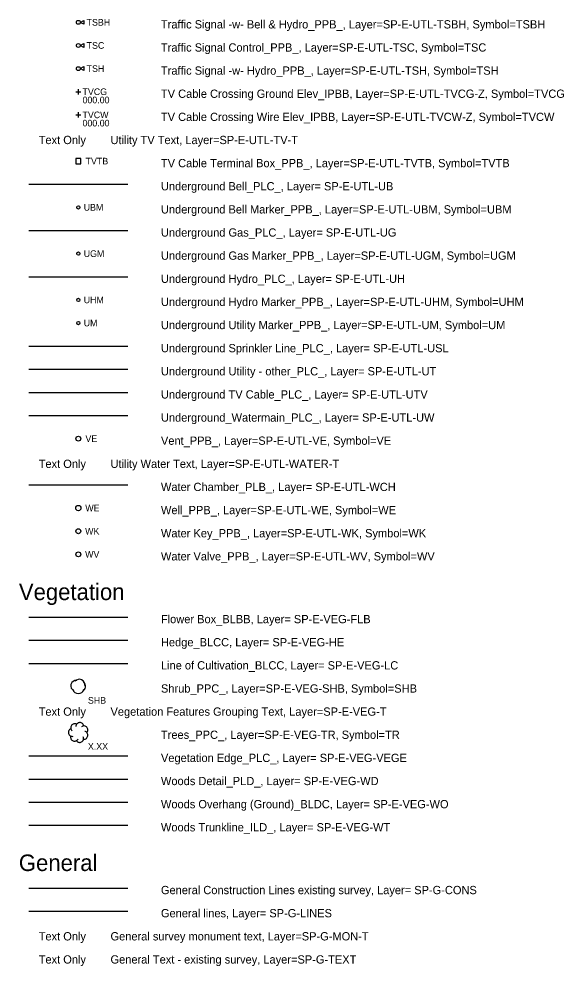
# Model space of a CAD drawing. Extents: x 500528 to 502626, y 4210261 to 4212624.
# Drawn here: x 501383.6 to 501548.5, y 4210563 to 4210849.6 of the extents above; entities that cross this region are included whole.
import ezdxf

# ---------------------------------------------------------------- set-up
doc = ezdxf.new("R2010")
doc.units = 0
for name, color, linetype in [('Default', 7, 'Continuous'), ('SP-E-UTL-BELL-T', 7, 'Continuous'), ('SP-E-UTL-COMB-T', 7, 'Continuous'), ('SP-E-UTL-GAS-T', 7, 'Continuous'), ('SP-E-UTL-HYDRO-T', 7, 'Continuous'), ('SP-E-UTL-T', 7, 'Continuous'), ('SP-E-UTL-TRAFFIC-T', 7, 'Continuous'), ('SP-E-UTL-TSBH', 7, 'Continuous'), ('SP-E-UTL-TSC', 7, 'Continuous'), ('SP-E-UTL-TSH', 7, 'Continuous'), ('SP-E-UTL-TV-T', 7, 'Continuous'), ('SP-E-UTL-TVCG-Z', 7, 'Continuous'), ('SP-E-UTL-TVCW-Z', 7, 'Continuous'), ('SP-E-UTL-TVTB', 7, 'Continuous'), ('SP-E-UTL-UB', 7, 'Continuous'), ('SP-E-UTL-UBM', 7, 'Continuous'), ('SP-E-UTL-UG', 7, 'Continuous'), ('SP-E-UTL-UGM', 7, 'Continuous'), ('SP-E-UTL-UH', 7, 'Continuous'), ('SP-E-UTL-UHM', 7, 'Continuous'), ('SP-E-UTL-UM', 7, 'Continuous'), ('SP-E-UTL-USL', 7, 'Continuous'), ('SP-E-UTL-UT', 7, 'Continuous'), ('SP-E-UTL-UTV', 7, 'Continuous'), ('SP-E-UTL-UW', 7, 'Continuous'), ('SP-E-UTL-VE', 7, 'Continuous'), ('SP-E-UTL-WATER-T', 7, 'Continuous'), ('SP-E-UTL-WCH', 7, 'Continuous'), ('SP-E-UTL-WE', 7, 'Continuous'), ('SP-E-UTL-WK', 7, 'Continuous'), ('SP-E-UTL-WV', 7, 'Continuous'), ('SP-E-VEG-FLB', 7, 'Continuous'), ('SP-E-VEG-HE', 7, 'Continuous'), ('SP-E-VEG-LC', 7, 'Continuous'), ('SP-E-VEG-SHB', 7, 'Continuous'), ('SP-E-VEG-T', 7, 'Continuous'), ('SP-E-VEG-TR', 7, 'Continuous'), ('SP-E-VEG-VEGE', 7, 'Continuous'), ('SP-E-VEG-WD', 7, 'Continuous'), ('SP-E-VEG-WO', 7, 'Continuous'), ('SP-E-VEG-WT', 7, 'Continuous'), ('SP-G-CONS', 7, 'Continuous'), ('SP-G-LINES', 7, 'Continuous'), ('SP-G-MON-T', 7, 'Continuous'), ('SP-G-TEXT', 7, 'Continuous')]:
    doc.layers.add(name, color=color, linetype=linetype)

# ---------------------------------------------------------------- blocks, each defined once
blk = doc.blocks.new('TSBH')
at = {"layer": 'SP-E-UTL-TSBH'}
for points in [[(0, 0), (0, 0)], [(0.058, 0), (0.162, 0.06), (0.162, -0.06), (0.058, 0)]]:
    blk.add_lwpolyline(points, dxfattribs=at)
blk.add_circle((0, 0), 0.0585, dxfattribs=at)
at = {"layer": 'SP-E-UTL-COMB-T'}
blk.add_text('TSBH', height=0.2, dxfattribs=at).set_placement((0.251, -0.1))
blk = doc.blocks.new('TSC')
at = {"layer": 'SP-E-UTL-TSC'}
for points in [[(0, 0), (0, 0)], [(0.058, 0), (0.162, 0.06), (0.162, -0.06), (0.058, 0)]]:
    blk.add_lwpolyline(points, dxfattribs=at)
blk.add_circle((0, 0), 0.0585, dxfattribs=at)
at = {"layer": 'SP-E-UTL-TRAFFIC-T'}
blk.add_text('TSC', height=0.2, dxfattribs=at).set_placement((0.251, -0.1))
blk = doc.blocks.new('TSH')
at = {"layer": 'SP-E-UTL-TSH'}
for points in [[(0, 0), (0, 0)], [(0.058, 0), (0.162, 0.06), (0.162, -0.06), (0.058, 0)]]:
    blk.add_lwpolyline(points, dxfattribs=at)
blk.add_circle((0, 0), 0.0585, dxfattribs=at)
at = {"layer": 'SP-E-UTL-COMB-T'}
blk.add_text('TSH', height=0.2, dxfattribs=at).set_placement((0.251, -0.1))
blk = doc.blocks.new('TVCG')
at = {"layer": 'SP-E-UTL-TVCG-Z'}
for points in [[(-0.08, 0), (0.08, 0)], [(0, -0.08), (0, 0.08)]]:
    blk.add_lwpolyline(points, dxfattribs=at)
at = {"layer": 'SP-E-UTL-TV-T'}
for s, p in [('TVCG', (0.126, -0.1)), ('000.00', (0.126, -0.35))]:
    blk.add_text(s, height=0.2, dxfattribs=at).set_placement(p)
blk = doc.blocks.new('TVCW')
at = {"layer": 'SP-E-UTL-TVCW-Z'}
for points in [[(-0.08, 0), (0.08, 0)], [(0, -0.08), (0, 0.08)]]:
    blk.add_lwpolyline(points, dxfattribs=at)
at = {"layer": 'SP-E-UTL-TV-T'}
for s, p in [('TVCW', (0.126, -0.1)), ('000.00', (0.126, -0.35))]:
    blk.add_text(s, height=0.2, dxfattribs=at).set_placement(p)
blk = doc.blocks.new('TVTB')
at = {"layer": 'SP-E-UTL-TVTB'}
blk.add_lwpolyline([(-0.08, 0.08), (-0.08, -0.08), (0.08, -0.08), (0.08, 0.08), (-0.08, 0.08)], dxfattribs=at)
at = {"layer": 'SP-E-UTL-TV-T'}
blk.add_text('TVTB', height=0.2, dxfattribs=at).set_placement((0.22, -0.1))
blk = doc.blocks.new('UBM')
at = {"layer": 'SP-E-UTL-UBM'}
blk.add_lwpolyline([(0, 0), (0, 0)], dxfattribs=at)
blk.add_circle((0, 0), 0.05, dxfattribs=at)
at = {"layer": 'SP-E-UTL-BELL-T'}
blk.add_text('UBM', height=0.2, dxfattribs=at).set_placement((0.162, -0.1))
blk = doc.blocks.new('UGM')
at = {"layer": 'SP-E-UTL-UGM'}
blk.add_lwpolyline([(0, 0), (0, 0)], dxfattribs=at)
blk.add_circle((0, 0), 0.05, dxfattribs=at)
at = {"layer": 'SP-E-UTL-GAS-T'}
blk.add_text('UGM', height=0.2, dxfattribs=at).set_placement((0.162, -0.1))
blk = doc.blocks.new('UHM')
at = {"layer": 'SP-E-UTL-UHM'}
blk.add_lwpolyline([(0, 0), (0, 0)], dxfattribs=at)
blk.add_circle((0, 0), 0.05, dxfattribs=at)
at = {"layer": 'SP-E-UTL-HYDRO-T'}
blk.add_text('UHM', height=0.2, dxfattribs=at).set_placement((0.162, -0.1))
blk = doc.blocks.new('UM')
at = {"layer": 'SP-E-UTL-UM'}
blk.add_lwpolyline([(0, 0), (0, 0)], dxfattribs=at)
blk.add_circle((0, 0), 0.05, dxfattribs=at)
at = {"layer": 'SP-E-UTL-T'}
blk.add_text('UM', height=0.2, dxfattribs=at).set_placement((0.162, -0.1))
blk = doc.blocks.new('VE')
at = {"layer": 'SP-E-UTL-VE'}
blk.add_lwpolyline([(0, 0), (0, 0)], dxfattribs=at)
blk.add_circle((0, 0), 0.075, dxfattribs=at)
at = {"layer": 'SP-E-UTL-T'}
blk.add_text('VE', height=0.2, dxfattribs=at).set_placement((0.215, -0.1))
blk = doc.blocks.new('WE')
at = {"layer": 'SP-E-UTL-WE'}
blk.add_lwpolyline([(0, 0), (0, 0)], dxfattribs=at)
blk.add_circle((0, 0), 0.08, dxfattribs=at)
at = {"layer": 'SP-E-UTL-T'}
blk.add_text('WE', height=0.2, dxfattribs=at).set_placement((0.211, -0.1))
blk = doc.blocks.new('WK')
at = {"layer": 'SP-E-UTL-WK'}
blk.add_lwpolyline([(0, 0), (0, 0)], dxfattribs=at)
blk.add_circle((0, 0), 0.075, dxfattribs=at)
at = {"layer": 'SP-E-UTL-WATER-T'}
blk.add_text('WK', height=0.2, dxfattribs=at).set_placement((0.206, -0.1))
blk = doc.blocks.new('WV')
at = {"layer": 'SP-E-UTL-WV'}
blk.add_lwpolyline([(0, 0), (0, 0)], dxfattribs=at)
blk.add_circle((0, 0), 0.075, dxfattribs=at)
at = {"layer": 'SP-E-UTL-WATER-T'}
blk.add_text('WV', height=0.2, dxfattribs=at).set_placement((0.206, -0.1))
blk = doc.blocks.new('SHB')
at = {"layer": 'SP-E-VEG-SHB'}
for centre, radius, start, end in [((-0.069, 0.02), 0.161, 80.6965, 246.9293), ((0.031, 0.052), 0.166, 353.6146, 139.6631), ((0.045, 0.007), 0.172, 296.4869, 48.0431), ((0, -0.044), 0.172, 193.3596, 346.7738)]:
    blk.add_arc(centre, radius, start, end, dxfattribs=at)
at = {"layer": 'SP-E-VEG-T'}
blk.add_text('SHB', height=0.2, dxfattribs=at).set_placement((0.29, -0.52))
blk = doc.blocks.new('TR')
at = {"layer": 'SP-E-VEG-TR'}
for points in [[(0.165, 0.205), (0.16, 0.227), (0.15, 0.247), (0.138, 0.266), (0.122, 0.281), (0.103, 0.293), (0.082, 0.302), (0.061, 0.307), (0.038, 0.307), (0.016, 0.304), (-0.005, 0.296), (-0.024, 0.285), (-0.041, 0.27), (-0.054, 0.252), (-0.065, 0.233), (-0.071, 0.211), (-0.074, 0.189)], [(-0.226, 0.123), (-0.246, 0.113), (-0.264, 0.099), (-0.279, 0.083), (-0.29, 0.064), (-0.298, 0.043), (-0.302, 0.021), (-0.302, -0.001), (-0.297, -0.023), (-0.289, -0.044), (-0.277, -0.063), (-0.261, -0.079), (-0.243, -0.092), (-0.223, -0.102), (-0.202, -0.107), (-0.179, -0.109), (-0.157, -0.106)], [(-0.05, 0.258), (-0.071, 0.268), (-0.092, 0.273), (-0.115, 0.274), (-0.137, 0.272), (-0.158, 0.265), (-0.177, 0.254), (-0.195, 0.24), (-0.209, 0.223), (-0.22, 0.203), (-0.227, 0.182), (-0.23, 0.16), (-0.229, 0.138), (-0.224, 0.116), (-0.215, 0.096), (-0.202, 0.077), (-0.187, 0.062)], [(0.258, 0.004), (0.272, 0.022), (0.282, 0.041), (0.288, 0.063), (0.29, 0.085), (0.288, 0.107), (0.282, 0.129), (0.272, 0.149), (0.259, 0.166), (0.242, 0.181), (0.223, 0.193), (0.202, 0.201), (0.18, 0.205), (0.158, 0.205), (0.136, 0.201), (0.115, 0.192), (0.096, 0.18)], [(0.158, -0.194), (0.181, -0.194), (0.203, -0.19), (0.223, -0.181), (0.242, -0.169), (0.258, -0.153), (0.271, -0.135), (0.28, -0.115), (0.286, -0.093), (0.287, -0.071), (0.285, -0.049), (0.278, -0.028), (0.267, -0.008), (0.253, 0.009), (0.236, 0.024), (0.217, 0.035), (0.196, 0.042)], [(-0.23, -0.099), (-0.234, -0.121), (-0.235, -0.143), (-0.231, -0.165), (-0.224, -0.186), (-0.212, -0.205), (-0.197, -0.222), (-0.18, -0.235), (-0.16, -0.246), (-0.138, -0.252), (-0.116, -0.254), (-0.094, -0.252), (-0.073, -0.246), (-0.052, -0.237), (-0.035, -0.223), (-0.02, -0.207), (-0.008, -0.188)], [(-0.059, -0.24), (-0.045, -0.257), (-0.027, -0.272), (-0.008, -0.282), (0.013, -0.289), (0.035, -0.292), (0.058, -0.291), (0.079, -0.286), (0.1, -0.277), (0.118, -0.264), (0.134, -0.248), (0.146, -0.23), (0.155, -0.209), (0.16, -0.187), (0.16, -0.165), (0.157, -0.143), (0.149, -0.122)]]:
    blk.add_lwpolyline(points, dxfattribs=at)
at = {"layer": 'SP-E-VEG-T'}
blk.add_text('X.XX', height=0.2, dxfattribs=at).set_placement((0.29, -0.512))

msp = doc.modelspace()

# ---------------------------------------------------------------- linework, layer by layer
at = {"layer": 'SP-E-UTL-UB'}
msp.add_line((501386.55, 4210799.59), (501416.55, 4210799.59), dxfattribs=at)
at = {"layer": 'SP-E-UTL-UG'}
msp.add_line((501386.55, 4210785.59), (501416.55, 4210785.59), dxfattribs=at)
at = {"layer": 'SP-E-UTL-UH'}
msp.add_line((501386.55, 4210771.59), (501416.55, 4210771.59), dxfattribs=at)
at = {"layer": 'SP-E-UTL-USL'}
msp.add_line((501386.55, 4210750.59), (501416.55, 4210750.59), dxfattribs=at)
at = {"layer": 'SP-E-UTL-UT'}
msp.add_line((501386.55, 4210743.59), (501416.55, 4210743.59), dxfattribs=at)
at = {"layer": 'SP-E-UTL-UTV'}
msp.add_line((501386.55, 4210736.59), (501416.55, 4210736.59), dxfattribs=at)
at = {"layer": 'SP-E-UTL-UW'}
msp.add_line((501386.55, 4210729.59), (501416.55, 4210729.59), dxfattribs=at)
at = {"layer": 'SP-E-UTL-WCH'}
msp.add_line((501386.55, 4210708.59), (501416.55, 4210708.59), dxfattribs=at)
at = {"layer": 'SP-E-VEG-FLB'}
msp.add_line((501386.55, 4210668.59), (501416.55, 4210668.59), dxfattribs=at)
at = {"layer": 'SP-E-VEG-HE'}
msp.add_line((501386.55, 4210661.59), (501416.55, 4210661.59), dxfattribs=at)
at = {"layer": 'SP-E-VEG-LC'}
msp.add_line((501386.55, 4210654.59), (501416.55, 4210654.59), dxfattribs=at)
at = {"layer": 'SP-E-VEG-VEGE'}
msp.add_line((501386.55, 4210626.59), (501416.55, 4210626.59), dxfattribs=at)
at = {"layer": 'SP-E-VEG-WD'}
msp.add_line((501386.55, 4210619.59), (501416.55, 4210619.59), dxfattribs=at)
at = {"layer": 'SP-E-VEG-WO'}
msp.add_line((501386.55, 4210612.59), (501416.55, 4210612.59), dxfattribs=at)
at = {"layer": 'SP-E-VEG-WT'}
msp.add_line((501386.55, 4210605.59), (501416.55, 4210605.59), dxfattribs=at)
at = {"layer": 'SP-G-CONS'}
msp.add_line((501386.55, 4210586.59), (501416.55, 4210586.59), dxfattribs=at)
at = {"layer": 'SP-G-LINES'}
msp.add_line((501386.55, 4210579.59), (501416.55, 4210579.59), dxfattribs=at)

# ---------------------------------------------------------------- block references
at = {"layer": 'SP-E-UTL-TSBH', "xscale": 10, "yscale": 10}
msp.add_blockref('TSBH', (501401.55, 4210848.59), dxfattribs=at)
at = {"layer": 'SP-E-UTL-TSC', "xscale": 10, "yscale": 10}
msp.add_blockref('TSC', (501401.55, 4210841.59), dxfattribs=at)
at = {"layer": 'SP-E-UTL-TSH', "xscale": 10, "yscale": 10}
msp.add_blockref('TSH', (501401.55, 4210834.59), dxfattribs=at)
at = {"layer": 'SP-E-UTL-TVCG-Z', "xscale": 10, "yscale": 10}
msp.add_blockref('TVCG', (501401.55, 4210827.59), dxfattribs=at)
at = {"layer": 'SP-E-UTL-TVCW-Z', "xscale": 10, "yscale": 10}
msp.add_blockref('TVCW', (501401.55, 4210820.59), dxfattribs=at)
at = {"layer": 'SP-E-UTL-TVTB', "xscale": 10, "yscale": 10}
msp.add_blockref('TVTB', (501401.55, 4210806.59), dxfattribs=at)
at = {"layer": 'SP-E-UTL-UBM', "xscale": 10, "yscale": 10}
msp.add_blockref('UBM', (501401.55, 4210792.59), dxfattribs=at)
at = {"layer": 'SP-E-UTL-UGM', "xscale": 10, "yscale": 10}
msp.add_blockref('UGM', (501401.55, 4210778.59), dxfattribs=at)
at = {"layer": 'SP-E-UTL-UHM', "xscale": 10, "yscale": 10}
msp.add_blockref('UHM', (501401.55, 4210764.59), dxfattribs=at)
at = {"layer": 'SP-E-UTL-UM', "xscale": 10, "yscale": 10}
msp.add_blockref('UM', (501401.55, 4210757.59), dxfattribs=at)
at = {"layer": 'SP-E-UTL-VE', "xscale": 10, "yscale": 10}
msp.add_blockref('VE', (501401.55, 4210722.59), dxfattribs=at)
at = {"layer": 'SP-E-UTL-WE', "xscale": 10, "yscale": 10}
msp.add_blockref('WE', (501401.55, 4210701.59), dxfattribs=at)
at = {"layer": 'SP-E-UTL-WK', "xscale": 10, "yscale": 10}
msp.add_blockref('WK', (501401.55, 4210694.59), dxfattribs=at)
at = {"layer": 'SP-E-UTL-WV', "xscale": 10, "yscale": 10}
msp.add_blockref('WV', (501401.55, 4210687.59), dxfattribs=at)
at = {"layer": 'SP-E-VEG-SHB', "xscale": 10, "yscale": 10}
msp.add_blockref('SHB', (501401.55, 4210647.59), dxfattribs=at)
at = {"layer": 'SP-E-VEG-TR', "xscale": 10, "yscale": 10}
msp.add_blockref('TR', (501401.55, 4210633.59), dxfattribs=at)

# ---------------------------------------------------------------- texts
at = {"layer": 'Default'}
for s, p in [('Vegetation ', (501383.55, 4210673.74)), ('General ', (501383.55, 4210591.74))]:
    msp.add_text(s, height=5, dxfattribs=at).set_placement(p)
at = {"layer": 'SP-E-UTL-TSBH'}
msp.add_text('Traffic Signal -w- Bell & Hydro_PPB_, Layer=SP-E-UTL-TSBH, Symbol=TSBH ', height=2.5, dxfattribs=at).set_placement((501426.55, 4210846.74))
at = {"layer": 'SP-E-UTL-TSC'}
msp.add_text('Traffic Signal Control_PPB_, Layer=SP-E-UTL-TSC, Symbol=TSC ', height=2.5, dxfattribs=at).set_placement((501426.55, 4210839.74))
at = {"layer": 'SP-E-UTL-TSH'}
msp.add_text('Traffic Signal -w- Hydro_PPB_, Layer=SP-E-UTL-TSH, Symbol=TSH ', height=2.5, dxfattribs=at).set_placement((501426.55, 4210832.74))
at = {"layer": 'SP-E-UTL-TV-T'}
msp.add_text('Text Only        Utility TV Text, Layer=SP-E-UTL-TV-T', height=2.5, dxfattribs=at).set_placement((501389.55, 4210811.74))
at = {"layer": 'SP-E-UTL-TVCG-Z'}
msp.add_text('TV Cable Crossing Ground Elev_IPBB, Layer=SP-E-UTL-TVCG-Z, Symbol=TVCG ', height=2.5, dxfattribs=at).set_placement((501426.55, 4210825.74))
at = {"layer": 'SP-E-UTL-TVCW-Z'}
msp.add_text('TV Cable Crossing Wire Elev_IPBB, Layer=SP-E-UTL-TVCW-Z, Symbol=TVCW ', height=2.5, dxfattribs=at).set_placement((501426.55, 4210818.74))
at = {"layer": 'SP-E-UTL-TVTB'}
msp.add_text('TV Cable Terminal Box_PPB_, Layer=SP-E-UTL-TVTB, Symbol=TVTB ', height=2.5, dxfattribs=at).set_placement((501426.55, 4210804.74))
at = {"layer": 'SP-E-UTL-UB'}
msp.add_text('Underground Bell_PLC_, Layer= SP-E-UTL-UB ', height=2.5, dxfattribs=at).set_placement((501426.55, 4210797.74))
at = {"layer": 'SP-E-UTL-UBM'}
msp.add_text('Underground Bell Marker_PPB_, Layer=SP-E-UTL-UBM, Symbol=UBM ', height=2.5, dxfattribs=at).set_placement((501426.55, 4210790.74))
at = {"layer": 'SP-E-UTL-UG'}
msp.add_text('Underground Gas_PLC_, Layer= SP-E-UTL-UG ', height=2.5, dxfattribs=at).set_placement((501426.55, 4210783.74))
at = {"layer": 'SP-E-UTL-UGM'}
msp.add_text('Underground Gas Marker_PPB_, Layer=SP-E-UTL-UGM, Symbol=UGM ', height=2.5, dxfattribs=at).set_placement((501426.55, 4210776.74))
at = {"layer": 'SP-E-UTL-UH'}
msp.add_text('Underground Hydro_PLC_, Layer= SP-E-UTL-UH ', height=2.5, dxfattribs=at).set_placement((501426.55, 4210769.74))
at = {"layer": 'SP-E-UTL-UHM'}
msp.add_text('Underground Hydro Marker_PPB_, Layer=SP-E-UTL-UHM, Symbol=UHM ', height=2.5, dxfattribs=at).set_placement((501426.55, 4210762.74))
at = {"layer": 'SP-E-UTL-UM'}
msp.add_text('Underground Utility Marker_PPB_, Layer=SP-E-UTL-UM, Symbol=UM ', height=2.5, dxfattribs=at).set_placement((501426.55, 4210755.74))
at = {"layer": 'SP-E-UTL-USL'}
msp.add_text('Underground Sprinkler Line_PLC_, Layer= SP-E-UTL-USL ', height=2.5, dxfattribs=at).set_placement((501426.55, 4210748.74))
at = {"layer": 'SP-E-UTL-UT'}
msp.add_text('Underground Utility - other_PLC_, Layer= SP-E-UTL-UT ', height=2.5, dxfattribs=at).set_placement((501426.55, 4210741.74))
at = {"layer": 'SP-E-UTL-UTV'}
msp.add_text('Underground TV Cable_PLC_, Layer= SP-E-UTL-UTV ', height=2.5, dxfattribs=at).set_placement((501426.55, 4210734.74))
at = {"layer": 'SP-E-UTL-UW'}
msp.add_text('Underground_Watermain_PLC_, Layer= SP-E-UTL-UW ', height=2.5, dxfattribs=at).set_placement((501426.55, 4210727.74))
at = {"layer": 'SP-E-UTL-VE'}
msp.add_text('Vent_PPB_, Layer=SP-E-UTL-VE, Symbol=VE ', height=2.5, dxfattribs=at).set_placement((501426.55, 4210720.74))
at = {"layer": 'SP-E-UTL-WATER-T'}
msp.add_text('Text Only        Utility Water Text, Layer=SP-E-UTL-WATER-T', height=2.5, dxfattribs=at).set_placement((501389.55, 4210713.74))
at = {"layer": 'SP-E-UTL-WCH'}
msp.add_text('Water Chamber_PLB_, Layer= SP-E-UTL-WCH ', height=2.5, dxfattribs=at).set_placement((501426.55, 4210706.74))
at = {"layer": 'SP-E-UTL-WE'}
msp.add_text('Well_PPB_, Layer=SP-E-UTL-WE, Symbol=WE ', height=2.5, dxfattribs=at).set_placement((501426.55, 4210699.74))
at = {"layer": 'SP-E-UTL-WK'}
msp.add_text('Water Key_PPB_, Layer=SP-E-UTL-WK, Symbol=WK ', height=2.5, dxfattribs=at).set_placement((501426.55, 4210692.74))
at = {"layer": 'SP-E-UTL-WV'}
msp.add_text('Water Valve_PPB_, Layer=SP-E-UTL-WV, Symbol=WV ', height=2.5, dxfattribs=at).set_placement((501426.55, 4210685.74))
at = {"layer": 'SP-E-VEG-FLB'}
msp.add_text('Flower Box_BLBB, Layer= SP-E-VEG-FLB ', height=2.5, dxfattribs=at).set_placement((501426.55, 4210666.74))
at = {"layer": 'SP-E-VEG-HE'}
msp.add_text('Hedge_BLCC, Layer= SP-E-VEG-HE ', height=2.5, dxfattribs=at).set_placement((501426.55, 4210659.74))
at = {"layer": 'SP-E-VEG-LC'}
msp.add_text('Line of Cultivation_BLCC, Layer= SP-E-VEG-LC ', height=2.5, dxfattribs=at).set_placement((501426.55, 4210652.74))
at = {"layer": 'SP-E-VEG-SHB'}
msp.add_text('Shrub_PPC_, Layer=SP-E-VEG-SHB, Symbol=SHB ', height=2.5, dxfattribs=at).set_placement((501426.55, 4210645.74))
at = {"layer": 'SP-E-VEG-T'}
msp.add_text('Text Only        Vegetation Features Grouping Text, Layer=SP-E-VEG-T', height=2.5, dxfattribs=at).set_placement((501389.55, 4210638.74))
at = {"layer": 'SP-E-VEG-TR'}
msp.add_text('Trees_PPC_, Layer=SP-E-VEG-TR, Symbol=TR ', height=2.5, dxfattribs=at).set_placement((501426.55, 4210631.74))
at = {"layer": 'SP-E-VEG-VEGE'}
msp.add_text('Vegetation Edge_PLC_, Layer= SP-E-VEG-VEGE ', height=2.5, dxfattribs=at).set_placement((501426.55, 4210624.74))
at = {"layer": 'SP-E-VEG-WD'}
msp.add_text('Woods Detail_PLD_, Layer= SP-E-VEG-WD ', height=2.5, dxfattribs=at).set_placement((501426.55, 4210617.74))
at = {"layer": 'SP-E-VEG-WO'}
msp.add_text('Woods Overhang (Ground)_BLDC, Layer= SP-E-VEG-WO ', height=2.5, dxfattribs=at).set_placement((501426.55, 4210610.74))
at = {"layer": 'SP-E-VEG-WT'}
msp.add_text('Woods Trunkline_ILD_, Layer= SP-E-VEG-WT ', height=2.5, dxfattribs=at).set_placement((501426.55, 4210603.74))
at = {"layer": 'SP-G-CONS'}
msp.add_text('General Construction Lines existing survey, Layer= SP-G-CONS ', height=2.5, dxfattribs=at).set_placement((501426.55, 4210584.74))
at = {"layer": 'SP-G-LINES'}
msp.add_text('General lines, Layer= SP-G-LINES ', height=2.5, dxfattribs=at).set_placement((501426.55, 4210577.74))
at = {"layer": 'SP-G-MON-T'}
msp.add_text('Text Only        General survey monument text, Layer=SP-G-MON-T', height=2.5, dxfattribs=at).set_placement((501389.55, 4210570.74))
at = {"layer": 'SP-G-TEXT'}
msp.add_text('Text Only        General Text - existing survey, Layer=SP-G-TEXT', height=2.5, dxfattribs=at).set_placement((501389.55, 4210563.74))

doc.saveas('drawing.dxf')
